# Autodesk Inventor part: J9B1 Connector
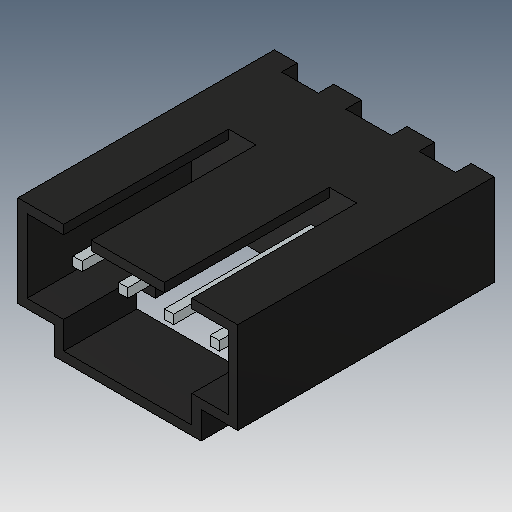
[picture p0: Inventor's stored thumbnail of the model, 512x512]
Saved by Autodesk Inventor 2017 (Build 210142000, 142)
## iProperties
Created: 2005-12
Part Number: J9B1 Connector
Material: Generic
Document SubType Name: Modeling
Designer: DanielSeverino
Density: 1 g/cm^3
Appearance: Default
Author: DanielSeverino
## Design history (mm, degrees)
feature "Solid1"
body "Solid2"
